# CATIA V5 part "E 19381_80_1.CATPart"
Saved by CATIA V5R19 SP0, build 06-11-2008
Definition: E 19381_80_1
Nomenclature: E 19381_80_1
Description: PART--DESC
Material "Plastic": density 1200 kg/m3, Young's modulus 2.2e+09 Pa, Poisson ratio 0.38, thermal expansion 6.84e-05 1/K
Bounding box of the stored display mesh (mm): x -15 to 65, y -17.5 to 17.5, z 0 to 21.1
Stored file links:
  G:\UTB\Kombinované\Bakalářská práce\Catia\FORMA\E 19381_80_1.CATPart
  D:\Aplikace\CATIA\Nová složka\win_b64\startup\materials\Catalog.CATMaterial
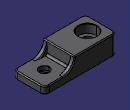
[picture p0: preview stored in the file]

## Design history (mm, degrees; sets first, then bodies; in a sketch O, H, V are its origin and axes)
Body1 "E 19381_80" (main body)
  Solid1: solid without history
